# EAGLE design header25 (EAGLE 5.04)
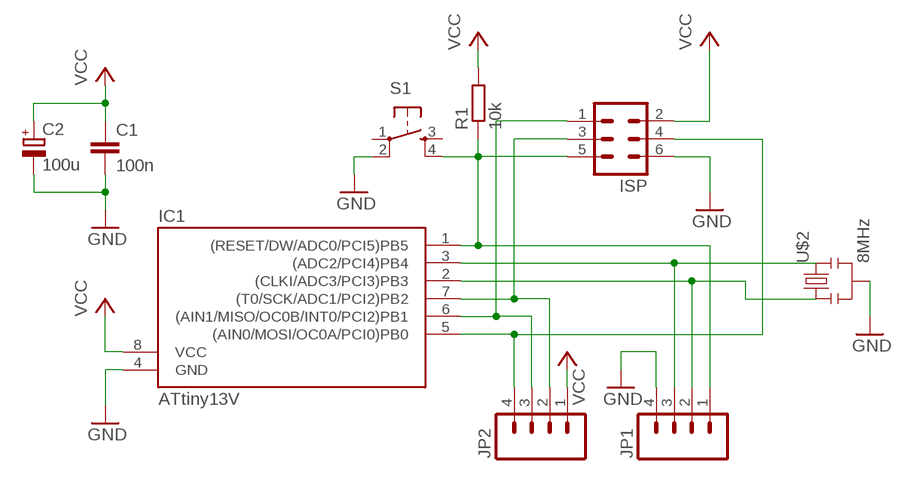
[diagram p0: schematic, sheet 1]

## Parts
C1  100n  C-EU025-025X050  [C025-025X050]
C2  100u  CPOL-EUE2,5-6E  [E2,5-6E]
IC1  ATtiny13V  ATTINY13-20P  [DIL08]
ISP  MA03-2  [MA03-2]
JP1  M04PTH  [1X04]
JP2  M04PTH  [1X04]
R1  10k  R-EU_0207/5V  [0207/5V]
S1  TAC_SWITCHPTH  [TACTILE-PTH]
U$2  8MHz  RESONATORPTH  [RESONATOR-PTH]

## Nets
GND: C1.2 C2.- IC1.4(GND) ISP.6 JP1.4 S1.2 U$2.2
N$2: IC1.2((CLKI/ADC3/PCI3)PB3) JP1.2 U$2.1
N$4: IC1.1((RESET/DW/ADC0/PCI5)PB5) ISP.5 JP1.1 R1.1 S1.4
N$5: IC1.7((T0/SCK/ADC1/PCI2)PB2) ISP.3 JP2.2
N$6: IC1.6((AIN1/MISO/OC0B/INT0/PCI2)PB1) ISP.1 JP2.3
N$8: IC1.3((ADC2/PCI4)PB4) JP1.3 U$2.3
N$10: IC1.5((AIN0/MOSI/OC0A/PCI0)PB0) ISP.4 JP2.4
VCC: C1.1 C2.+ IC1.8(VCC) ISP.2 JP2.1 R1.2
Unconnected: S1.1 S1.3

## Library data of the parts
C1 = rcl:C-EU: CAPACITOR, European symbol
C2 = rcl:CPOL-EU: POLARIZED CAPACITOR, European symbol
IC1 = avr:ATTINY13: MICROCONTROLLER 1 Kbytes FLASH 64 bytes EEPROM 64 bytes RAM 4-channel 10 bit ADC
ISP = con-lstb:MA03-2: PIN HEADER
JP1 JP2 = SparkFun:M04: Header 4 Standard 4-pin 0.1" header. Use with straight break away headers (SKU : PRT-00116), right angle break away headers (PRT-00553), swiss pins (PRT-00743), machine pins (PRT-00117), and female headers (PRT-00115). Molex polarized connector foot print use with SKU : PRT-08231 with associated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
R1 = rcl:R-EU_: RESISTOR, European symbol
S1 = SparkFun:TAC_SWITCH: Momentary Switch Button commonly used for reset or general input. Spark Fun Electronics SKU : COM-00097
U$2 = SparkFun:RESONATOR: Resonator Small SMD resonator. This is the itty bitty 10/20MHz resonators with built in caps. CSTCE10M0G55 and CSTCE20M0V53. Footprint has been reviewed closely but hasn't been tested yet.

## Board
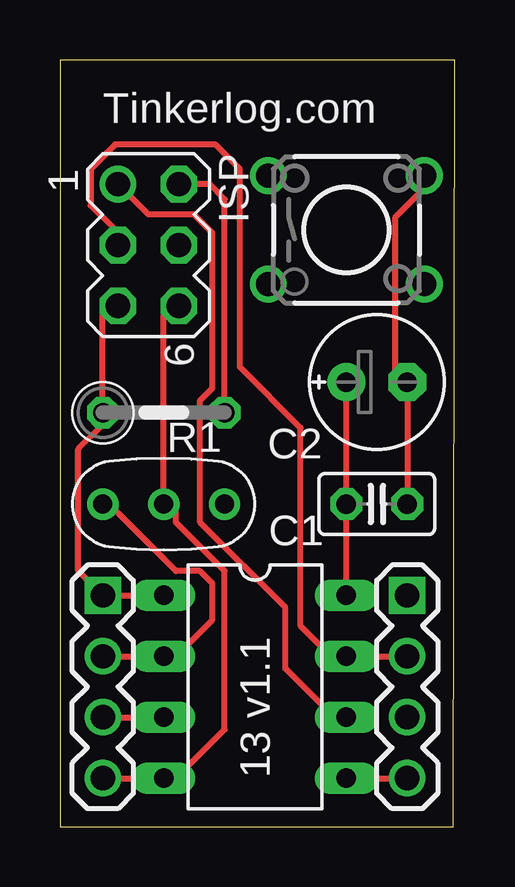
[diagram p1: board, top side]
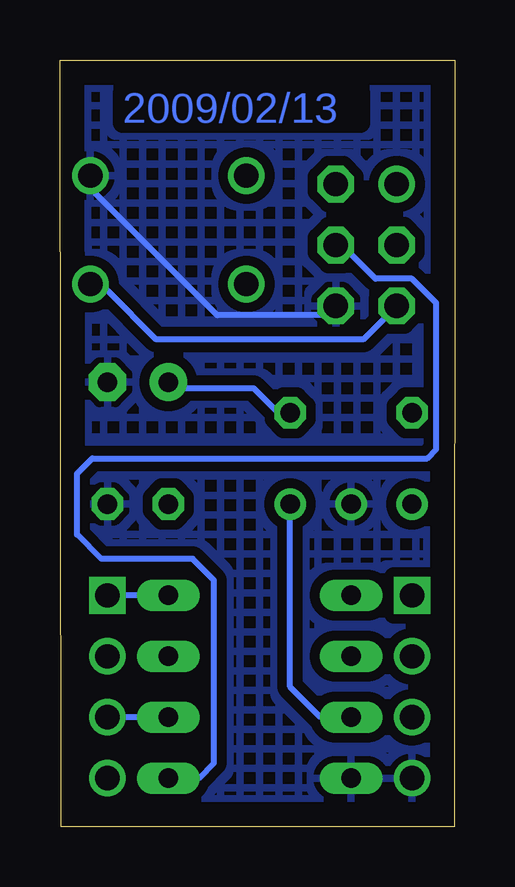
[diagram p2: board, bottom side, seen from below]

Size 16.47 x 31.96 mm. Coordinates in mm from the lower left corner, seen from the top.
Outline: 0.01,0 16.41,0 16.47,31.96 0,31.95 0.01,0
Copper layers (1*16): Top 0.035mm / dielectric 1.5mm / Bottom 0.035mm
Design rules "default": minimum track width 10mil, minimum drill 24mil, track to track 8mil, track to pad 8mil, pad to pad 8mil, via to via 8mil, smd to smd 8mil, copper to edge 40mil, drill to drill 8mil, minimum pad ring 10mil, minimum via ring 8mil, stop-mask expansion 4mil, vias tented up to drill 0mil, thermal gap 10mil

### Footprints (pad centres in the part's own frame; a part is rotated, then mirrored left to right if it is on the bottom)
C025-025X050 = drill 0.813 octagon: 1 -1.27,0; 2 1.27,0
E2,5-6E = drill 0.813 pad 1.575 round: + -1.27,0 | drill 0.813 pad 1.575 octagon: - 1.27,0
DIL08 = drill 0.813 long: 1 -3.81,-3.81; 2 -1.27,-3.81; 3 1.27,-3.81; 4 3.81,-3.81; 5 3.81,3.81; 6 1.27,3.81; 7 -1.27,3.81; 8 -3.81,3.81
MA03-2 = drill 1.016 round: 1 -2.54,-1.27 | drill 1.016 octagon: 2 -2.54,1.27; 3 0,-1.27; 4 0,1.27; 5 2.54,-1.27; 6 2.54,1.27
1X04 = drill 1.016 square: 1 0,0 | drill 1.016 round: 2 2.54,0; 3 5.08,0; 4 7.62,0
0207/5V = drill 0.813 octagon: 1 -2.54,0; 2 2.54,0
TACTILE-PTH = drill 1.016 round: 1 -3.251,2.261; 2 3.251,2.261; 3 -3.251,-2.261; 4 3.251,-2.261
RESONATOR-PTH = drill 0.8 round: 1 -2.54,0; 2 0,0; 3 2.54,0

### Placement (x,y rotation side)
C1  13.22,13.45 0 top
C2  13.22,18.53 0 top
IC1  8.14,5.83 270 top
ISP  3.69,24.24 270 top
JP1  1.79,9.64 270 top
JP2  14.49,9.64 270 top
R1  4.33,17.26 0 top
S1  11.95,24.88 0 top
U$2  4.33,13.45 0 top

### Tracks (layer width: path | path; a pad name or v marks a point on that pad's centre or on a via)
GND
  Top 0.254: C1.2 C2.- 13.98,18.78 13.98,25.39 14.99,26.4 S1.2 | JP1.4 IC1.4 5.34,2.53 6.87,4.05 6.87,10.66 4.83,12.69 4.83,13.2 U$2.2 4.33,21.32 ISP.6
  Bottom 0.254: S1.2 14.99,26.4 9.91,21.32 5.34,21.32 ISP.6
  pour Bottom (isolate 0.406, hatched): 0.01,31.74 0.01,-0.01 16.52,-0.01 16.52,31.74
N$2
  Top 0.254: U$2.1 2.29,13.2 4.83,10.66 5.85,10.66 6.36,10.15 6.36,8.62 5.34,7.61 IC1.2 JP1.2
N$4
  Top 0.254: IC1.1 JP1.1 0.77,10.66 0.77,15.74 1.79,16.75 R1.1 1.79,21.32 ISP.5
  Bottom 0.254: S1.4 14.49,22.34 12.45,20.31 3.82,20.31 ISP.5
N$5
  Top 0.254: JP2.2 IC1.7 11.31,7.1 10.04,8.37 10.04,16.62 7.5,19.16 7.5,27.42 6.48,28.44 2.29,28.44 1.28,27.42 1.28,25.9 2.29,24.88 ISP.3
N$6
  Top 0.254: IC1.6 10.93,5.07 9.41,6.59 9.41,9.13 5.85,12.69 5.85,17.77 6.36,18.28 6.36,24.75 5.6,25.51 3.69,25.51 ISP.1
  Bottom 0.254: IC1.6 JP2.3
N$8
  Top 0.254: JP1.3 IC1.3
  Bottom 0.254: IC1.3 5.6,4.56 6.87,5.83 U$2.3
N$10
  Top 0.254: IC1.5 JP2.4
  Bottom 0.254: ISP.4 4.33,23.86 3.31,22.85 1.79,22.85 0.77,21.83 0.77,15.74 1.15,15.35 15.12,15.35 15.76,14.72 15.76,12.18 14.74,11.16 10.93,11.16 10.04,10.27 10.04,2.65 10.68,2.02 IC1.5
VCC
  Top 0.254: IC1.8 C1.1 C2.+ | R1.2 6.87,26.15 6.23,26.78 ISP.2
  Bottom 0.254: IC1.8 JP2.1 | R1.2 7.37,17.26 8.39,18.28 11.44,18.28 C2.+

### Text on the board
Bottom: 2009/02/13
tPlace: Tinkerlog.com | 13 v1.1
